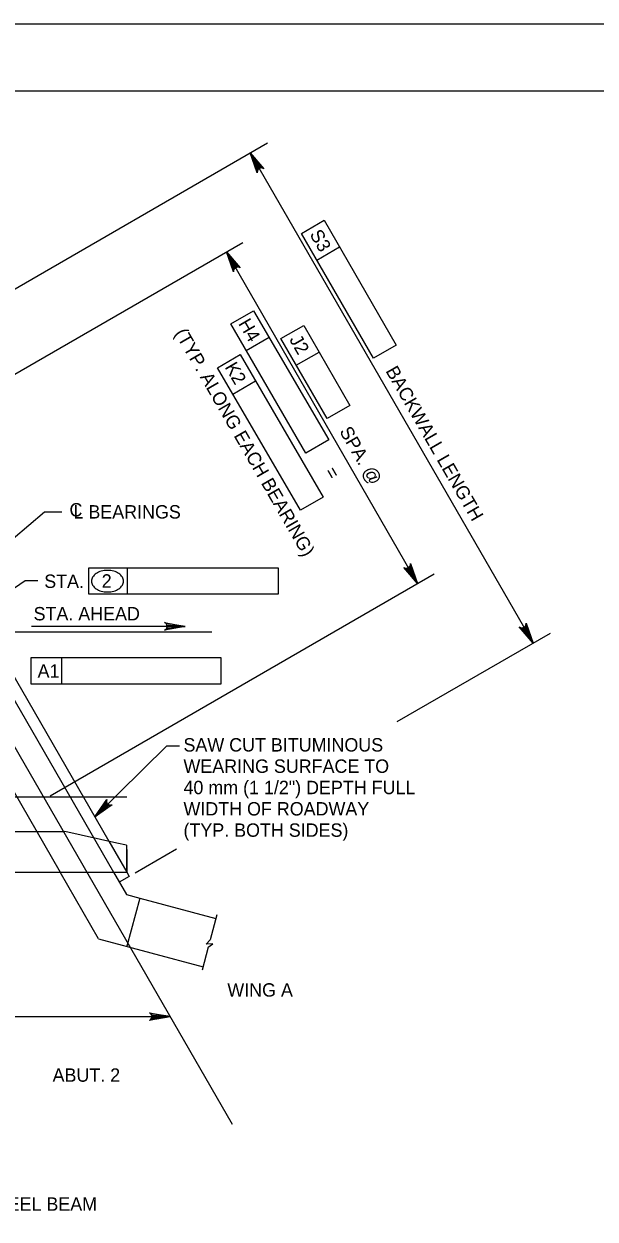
# Model space of a CAD drawing. Extents: x 638175 to 640495, y 294277 to 298435.
# Drawn here: x 639681.3 to 639809.5, y 298167.4 to 298435.5 of the extents above; entities that cross this region are included whole.
import ezdxf

# ---------------------------------------------------------------- set-up
doc = ezdxf.new("R2010")
doc.units = 0
for name, color, linetype in [('2', 7, 'Continuous'), ('3', 7, 'Continuous'), ('4', 7, 'Continuous'), ('PLT-BNDY', 7, 'Continuous')]:
    doc.layers.add(name, color=color, linetype=linetype)

msp = doc.modelspace()

# ---------------------------------------------------------------- linework, layer by layer
at = {"layer": '2'}
for p, q in [((639316.46, 298420.46), (640102.46, 298420.46)), ((639627.87, 298351.98), (639689.49, 298245.25)), ((639639.81, 298351.98), (639701.42, 298245.25)), ((639645.77, 298346.82), (639700.42, 298252.17)), ((639513.62, 298254.37), (639690.54, 298254.37)), ((639702.22, 298251.77), (639690.54, 298254.37)), ((639700.42, 298252.17), (639704.41, 298245.26)), ((639704.39, 298251.28), (639702.22, 298251.77)), ((639704.41, 298245.25), (639704.41, 298251.28)), ((639704.41, 298250.3), (639704.41, 298245.25)), ((639499.77, 298245.25), (639704.41, 298245.25)), ((639499.77, 298245.25), (639704.41, 298245.25)), ((639499.77, 298245.25), (639693.78, 298245.25)), ((639499.77, 298245.25), (639693.78, 298245.25)), ((639698.12, 298230.31), (639689.49, 298245.25)), ((639701.42, 298245.25), (639704.34, 298240.21)), ((639704.96, 298244.3), (639702.72, 298243.01)), ((639704.41, 298245.26), (639704.96, 298244.3)), ((639704.34, 298240.21), (639707.36, 298239.4)), ((639707.36, 298239.4), (639704.47, 298228.61)), ((639707.36, 298239.4), (639724.44, 298234.82)), ((639698.12, 298230.31), (639721.55, 298224.03))]:
    msp.add_line(p, q, dxfattribs=at)
at = {"layer": '3'}
for p, q in [((639601.55, 298407.9), (639728.11, 298188.7)), ((639724.67, 298235.66), (639723.16, 298230.06)), ((639722.72, 298228.39), (639721.35, 298223.27)), ((639722.27, 298229.08), (639723.16, 298230.06)), ((639723.77, 298229.17), (639722.27, 298229.08)), ((639722.72, 298228.39), (639723.77, 298229.17))]:
    msp.add_line(p, q, dxfattribs=at)
at = {"layer": '4'}
for p, q in [((639642.84, 298355.01), (639736.02, 298408.8)), ((639732.12, 298406.55), (639795.59, 298296.62)), ((639743.61, 298388.47), (639748.72, 298391.42)), ((639748.72, 298391.42), (639764.86, 298363.44)), ((639759.75, 298360.49), (639743.61, 298388.47)), ((639644.34, 298336.75), (639730.45, 298386.46)), ((639769.68, 298309.97), (639726.78, 298384.35)), ((639747.05, 298382.5), (639752.16, 298385.45)), ((639727.77, 298368.18), (639732.89, 298371.13)), ((639732.89, 298371.13), (639749.75, 298342.17)), ((639744.63, 298339.22), (639727.77, 298368.18)), ((639739.03, 298364.89), (639744.14, 298367.85)), ((639744.14, 298367.85), (639754.5, 298349.89)), ((639731.24, 298362.22), (639736.34, 298365.2)), ((639749.38, 298346.94), (639739.03, 298364.89)), ((639742.47, 298358.93), (639747.58, 298361.88)), ((639764.86, 298363.44), (639759.75, 298360.49)), ((639724.75, 298358.36), (639729.87, 298361.31)), ((639729.87, 298361.31), (639748.52, 298329.36)), ((639743.4, 298326.41), (639724.75, 298358.36)), ((639728.22, 298352.41), (639733.32, 298355.39)), ((639754.5, 298349.89), (639749.38, 298346.94)), ((639749.75, 298342.17), (639744.63, 298339.22)), ((639748.52, 298329.36), (639743.4, 298326.41)), ((639661.02, 298304.91), (639685.96, 298326.02)), ((639685.96, 298326.02), (639689.82, 298326.02)), ((639695.88, 298307.55), (639695.88, 298313.46)), ((639695.88, 298313.46), (639738.4, 298313.46)), ((639704.62, 298307.55), (639704.62, 298313.46)), ((639738.4, 298313.46), (639738.4, 298307.55)), ((639687.27, 298262.39), (639773.38, 298312.11)), ((639664.41, 298299.03), (639681.64, 298310.61)), ((639681.64, 298310.61), (639684.47, 298310.61)), ((639738.4, 298307.55), (639695.88, 298307.55)), ((639717.56, 298300.36), (639683.02, 298300.36)), ((639723.5, 298299.03), (639431.2, 298299.03)), ((639765.11, 298279.03), (639799.49, 298298.87)), ((639682.98, 298287.43), (639682.98, 298293.34)), ((639682.98, 298293.34), (639725.5, 298293.34)), ((639689.87, 298287.43), (639689.87, 298293.34)), ((639725.5, 298293.34), (639725.5, 298287.43)), ((639725.5, 298287.43), (639682.98, 298287.43)), ((639697.25, 298257.66), (639713.41, 298273.57)), ((639713.41, 298273.57), (639716.25, 298273.57)), ((639704.42, 298262.06), (639353.94, 298262.06)), ((639706.31, 298245.08), (639715.6, 298250.44)), ((639530.41, 298212.86), (639714.16, 298212.86)), ((639533.41, 298212.86), (639714.16, 298212.86))]:
    msp.add_line(p, q, dxfattribs=at)
for points in [[(639734.06, 298404.21), (639733.19, 298403.71), (639732.12, 298406.55)], [(639727.79, 298381.65), (639728.61, 298382.13), (639726.78, 298384.35)], [(639767.85, 298312.19), (639768.67, 298312.66), (639769.68, 298309.97)], [(639794.52, 298299.47), (639793.66, 298298.97), (639795.59, 298296.62)], [(639699.66, 298259.37), (639699, 298260.05), (639697.31, 298257.72)], [(639711.16, 298213.36), (639711.16, 298212.36), (639714.16, 298212.86)]]:
    msp.add_lwpolyline(points, close=True, dxfattribs=at)
for points in [[(639732.12, 298406.55), (639735.21, 298402.95), (639734.82, 298403.14), (639734.45, 298403.15), (639734.16, 298403.04), (639733.91, 298402.83), (639733.73, 298402.52), (639733.7, 298402.08), (639732.12, 298406.55), (639733.73, 298402.52), (639733.91, 298402.83), (639732.12, 298406.55), (639734.16, 298403.04), (639734.45, 298403.15), (639732.12, 298406.55), (639734.82, 298403.14)], [(639726.78, 298384.35), (639729.87, 298380.75), (639729.47, 298380.93), (639729.11, 298380.94), (639728.81, 298380.83), (639728.57, 298380.62), (639728.39, 298380.31), (639728.35, 298379.87), (639726.78, 298384.35), (639728.39, 298380.31), (639728.57, 298380.62), (639726.78, 298384.35), (639728.81, 298380.83), (639729.11, 298380.94), (639726.78, 298384.35), (639729.47, 298380.93)], [(639769.68, 298309.97), (639766.59, 298313.57), (639766.99, 298313.39), (639767.35, 298313.38), (639767.65, 298313.49), (639767.89, 298313.69), (639768.07, 298314.01), (639768.11, 298314.45), (639769.68, 298309.97), (639768.07, 298314.01), (639767.89, 298313.69), (639769.68, 298309.97), (639767.65, 298313.49), (639767.35, 298313.38), (639769.68, 298309.97), (639766.99, 298313.39)], [(639717.56, 298300.36), (639712.9, 298299.49), (639713.26, 298299.74), (639713.44, 298300.05), (639713.5, 298300.36), (639713.44, 298300.68), (639713.26, 298300.99), (639712.9, 298301.24), (639717.56, 298300.36), (639713.26, 298300.99), (639713.44, 298300.68), (639717.56, 298300.36), (639713.5, 298300.36), (639713.44, 298300.05), (639717.56, 298300.36), (639713.26, 298299.74)], [(639795.59, 298296.62), (639792.5, 298300.22), (639792.9, 298300.04), (639793.26, 298300.03), (639793.56, 298300.14), (639793.8, 298300.35), (639793.98, 298300.66), (639794.02, 298301.1), (639795.59, 298296.62), (639793.98, 298300.66), (639793.8, 298300.35), (639795.59, 298296.62), (639793.56, 298300.14), (639793.26, 298300.03), (639795.59, 298296.62), (639792.9, 298300.04)], [(639697.25, 298257.66), (639699.96, 298261.55), (639699.87, 298261.12), (639699.96, 298260.77), (639700.14, 298260.51), (639700.4, 298260.32), (639700.75, 298260.23), (639701.18, 298260.31), (639697.25, 298257.66), (639700.75, 298260.23), (639700.4, 298260.32), (639697.25, 298257.66), (639700.14, 298260.51), (639699.96, 298260.77), (639697.25, 298257.66), (639699.87, 298261.12)], [(639714.16, 298212.86), (639709.5, 298211.99), (639709.86, 298212.24), (639710.04, 298212.55), (639710.1, 298212.86), (639710.04, 298213.17), (639709.86, 298213.49), (639709.5, 298213.73), (639714.16, 298212.86), (639709.86, 298213.49), (639710.04, 298213.17), (639714.16, 298212.86), (639710.1, 298212.86), (639710.04, 298212.55), (639714.16, 298212.86), (639709.86, 298212.24)]]:
    msp.add_lwpolyline(points, dxfattribs=at)
for centre, radius, start, end in [((639698.2, 298310.49), 1.68, 148.5507, 180), ((639699.12, 298309.93), 2.75, 124.109, 148.5507), ((639699.72, 298309.05), 3.82, 105.6708, 124.109), ((639700.11, 298307.65), 5.27, 90, 105.6708), ((639700.11, 298307.65), 5.27, 74.3292, 90), ((639700.5, 298309.05), 3.82, 55.891, 74.3292), ((639701.1, 298309.93), 2.75, 31.4493, 55.891), ((639702.01, 298310.49), 1.68, 0, 31.4493), ((639698.2, 298310.49), 1.68, 180, 211.4493), ((639699.12, 298311.05), 2.75, 211.4493, 235.891), ((639699.72, 298311.94), 3.82, 235.891, 254.3292), ((639700.11, 298313.34), 5.27, 254.3292, 270), ((639700.11, 298313.34), 5.27, 270, 285.6708), ((639700.5, 298311.94), 3.82, 285.6708, 304.109), ((639701.1, 298311.05), 2.75, 304.109, 328.5507), ((639702.01, 298310.49), 1.68, 328.5507, 0)]:
    msp.add_arc(centre, radius, start, end, dxfattribs=at)
at = {"layer": 'PLT-BNDY'}
msp.add_lwpolyline([(639276.46, 298435.46), (640117.46, 298435.46), (640117.46, 297841.46), (639276.46, 297841.46)], close=True, dxfattribs=at)

# ---------------------------------------------------------------- texts
at = {"layer": '4'}
for s, rotation, p in [('S3', 299.9745, (639745.37, 298388.28)), ('H4', 300.2076, (639729.37, 298368.27)), ('(TYP. ALONG EACH BEARING)', 299.9745, (639715.09, 298366.12)), ('J2', 299.9745, (639740.8, 298364.69)), ('K2', 300.2756, (639726.32, 298358.51)), ('BACKWALL LENGTH', 299.9745, (639762.41, 298357.65)), ('SPA. @', 299.9745, (639752.05, 298344.11)), ('= ', 299.9745, (639748.69, 298335.07))]:
    msp.add_text(s, height=3, rotation=rotation, dxfattribs=at).set_placement(p)
for s, p in [('C', (639691.57, 298325)), ('L BEARINGS', (639692.47, 298324.54)), ('STA.', (639685.91, 298308.98)), ('2', (639698.81, 298309.04)), ('STA. AHEAD', (639683.52, 298301.7)), ('A1', (639684.42, 298288.86)), ('SAW CUT BITUMINOUS', (639717.15, 298272.29)), ('WEARING SURFACE TO', (639717.15, 298267.51)), ('40 mm (1 1/2") DEPTH FULL', (639717.15, 298262.73)), ('WIDTH OF ROADWAY', (639717.15, 298257.95)), ('(TYP. BOTH SIDES)', (639717.15, 298253.17)), ('WING A', (639726.99, 298217.33)), ('ABUT. 2', (639687.78, 298198.24)), ('C  STEEL BEAM', (639667.45, 298169.32))]:
    msp.add_text(s, height=3, dxfattribs=at).set_placement(p)

doc.saveas('drawing.dxf')
